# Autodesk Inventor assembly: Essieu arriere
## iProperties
Shininess: 41.0
Length Units: 11269
Angle Units: 11279
Time Units: 11290
Mass Units: 11283
Length Display Precision: 3
Angle Display Precision: 2
Compacted: True
Created: 2002-04
Part Number: Essieu arriere
Document SubType Name: Assemblage
Designer: Flavien MARTY
Density: 0.0
Volumn: 0.0
Area: 0.0
PropertySet Name: Model Information
Control State: 0
Master: False
Checked Out: False
Author: Flavien MARTY
